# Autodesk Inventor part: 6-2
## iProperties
Author: Administrator
Created: 2001-02
Part Number: 6-2
Document SubType Name: Modeling
Designer: Administrator
Control State: 0
Master: False
Checked Out: False
PropertySet Name: Design Tracking Control
Shininess: 20.0
PropertySet Name: _Private Model Information
Density: 0.0
Volumn: 0.0
Area: 0.0
PropertySet Name: Model Information
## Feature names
1. Extrusion1
2. Hole1
